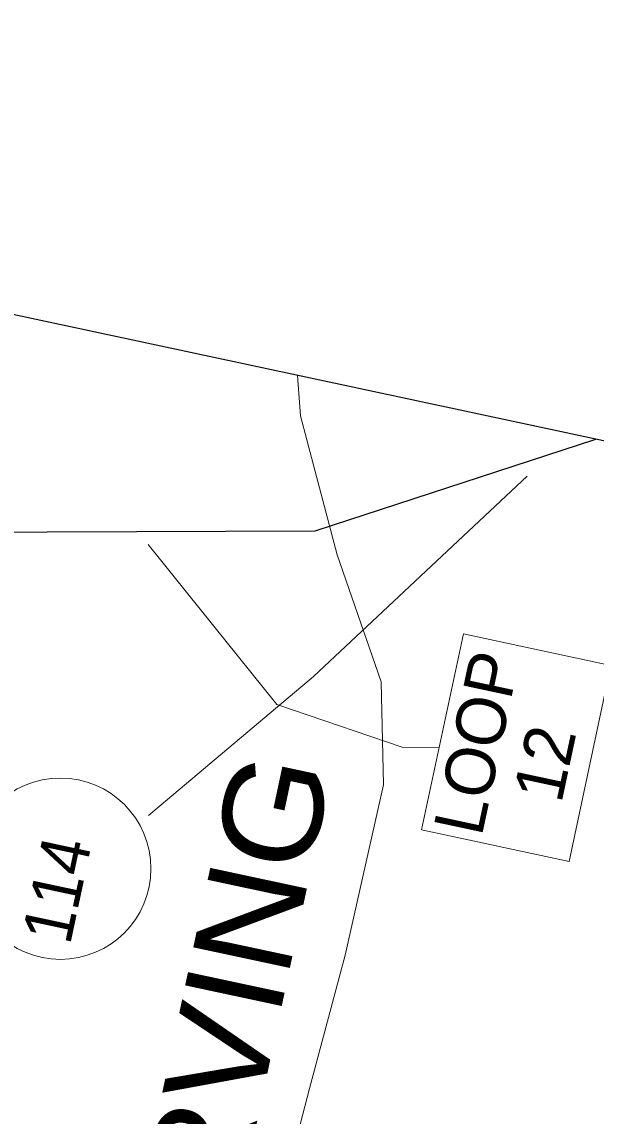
# Model space of a CAD drawing. Extents: x 2363411 to 2369126, y 6976878 to 6988319.
# Drawn here: x 2368241.1 to 2368300.5, y 6988181.5 to 6988294.5 of the extents above; entities that cross this region are included whole.
import ezdxf

# ---------------------------------------------------------------- set-up
doc = ezdxf.new("R2010")
doc.units = 0
doc.header["$LTSCALE"] = 2
doc.layers.add('62', color=7, linetype='Continuous', lineweight=13)
doc.layers.add('63', color=7, linetype='Continuous', lineweight=13)

msp = doc.modelspace()

# ---------------------------------------------------------------- linework, layer by layer
at = {"layer": '62'}
for p, q in [((2368271.271, 6988226.92), (2368293.362, 6988247.602)), ((2368271.271, 6988226.92), (2368254.22, 6988212.592)), ((2368280.462, 6988219.641), (2368284.264, 6988219.564))]:
    msp.add_line(p, q, dxfattribs=at)
at = {"layer": '62', "lineweight": 25}
for points in [[(2368004.774, 6987854.862), (2368459.776, 6987757.642), (2368553.719, 6988197.31), (2368098.715, 6988294.53)], [(2368213.143, 6988237.017), (2368234.49, 6988241.841), (2368271.473, 6988241.97), (2368300.459, 6988251.424)]]:
    msp.add_lwpolyline(points, dxfattribs=at)
at = {"layer": '62'}
for points in [[(2368260.308, 6988127.259), (2368262.282, 6988140.48), (2368265.488, 6988163.656), (2368270.883, 6988184.388), (2368274.562, 6988198.165), (2368278.528, 6988215.751), (2368278.264, 6988226.37), (2368273.748, 6988239.482), (2368269.937, 6988253.851), (2368269.65, 6988258.007)], [(2368280.462, 6988219.641), (2368267.502, 6988224.044), (2368254.212, 6988240.549)]]:
    msp.add_lwpolyline(points, dxfattribs=at)
msp.add_lwpolyline([(2368282.456, 6988211.091), (2368297.704, 6988207.835), (2368302.03, 6988228.078), (2368286.78, 6988231.337)], close=True, dxfattribs=at)
msp.add_circle((2368245.126, 6988207.082), 9.364, dxfattribs=at)
at = {"layer": '63'}
for p, q in [((2368271.271, 6988226.92), (2368293.362, 6988247.602)), ((2368271.271, 6988226.92), (2368254.22, 6988212.592)), ((2368280.462, 6988219.641), (2368284.264, 6988219.564))]:
    msp.add_line(p, q, dxfattribs=at)
at = {"layer": '63', "lineweight": 25}
for points in [[(2368004.774, 6987854.862), (2368459.776, 6987757.642), (2368553.719, 6988197.31), (2368098.715, 6988294.53)], [(2368213.143, 6988237.017), (2368234.49, 6988241.841), (2368271.473, 6988241.97), (2368300.459, 6988251.424)]]:
    msp.add_lwpolyline(points, dxfattribs=at)
at = {"layer": '63'}
for points in [[(2368260.308, 6988127.259), (2368262.282, 6988140.48), (2368265.488, 6988163.656), (2368270.883, 6988184.388), (2368274.562, 6988198.165), (2368278.528, 6988215.751), (2368278.264, 6988226.37), (2368273.748, 6988239.482), (2368269.937, 6988253.851), (2368269.65, 6988258.007)], [(2368280.462, 6988219.641), (2368267.502, 6988224.044), (2368254.212, 6988240.549)]]:
    msp.add_lwpolyline(points, dxfattribs=at)
msp.add_lwpolyline([(2368282.456, 6988211.091), (2368297.704, 6988207.835), (2368302.03, 6988228.078), (2368286.78, 6988231.337)], close=True, dxfattribs=at)
msp.add_circle((2368245.126, 6988207.082), 9.364, dxfattribs=at)

# ---------------------------------------------------------------- texts
at = {"layer": '62'}
for s, p in [('LOOP', (2368288.659, 6988210.297)), ('12', (2368296.891, 6988213.714))]:
    msp.add_text(s, height=5.099, rotation=77.939, dxfattribs=at).set_placement(p)
for s, height, width, p in [('IRVING', 10.21, 1.1, (2368262.487, 6988167.061)), ('114', 5.099, 0.95, (2368246.113, 6988199.093))]:
    msp.add_text(s, height=height, rotation=77.939, dxfattribs=dict(at, width=width)).set_placement(p)
at = {"layer": '63'}
for s, p in [('LOOP', (2368288.659, 6988210.297)), ('12', (2368296.891, 6988213.714))]:
    msp.add_text(s, height=5.099, rotation=77.939, dxfattribs=at).set_placement(p)
for s, height, width, p in [('IRVING', 10.21, 1.1, (2368262.487, 6988167.061)), ('114', 5.099, 0.95, (2368246.113, 6988199.093))]:
    msp.add_text(s, height=height, rotation=77.939, dxfattribs=dict(at, width=width)).set_placement(p)

doc.saveas('drawing.dxf')
